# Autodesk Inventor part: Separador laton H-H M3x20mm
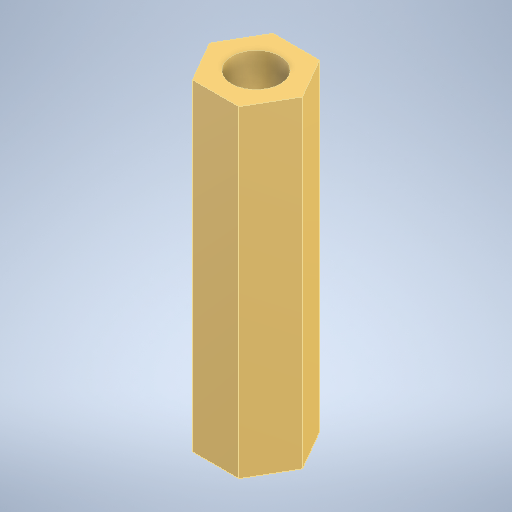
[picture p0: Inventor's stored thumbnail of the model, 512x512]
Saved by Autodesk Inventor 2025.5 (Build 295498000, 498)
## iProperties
Created: 2018-08
Part Number: Separador laton H-H M3x20mm
Material: solidworks materials|Latón
Document SubType Name: Modeling
Designer: Luis M
Density: 8.5 g/cm^3
Appearance: polished brass
Author: Luis M
Sending System: SolidWorks 2017
Last Author: Jonathan
Last Saved: 2018-08-15
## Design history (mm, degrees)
feature "Saliente-Extruir1"
node "Sólido1"
